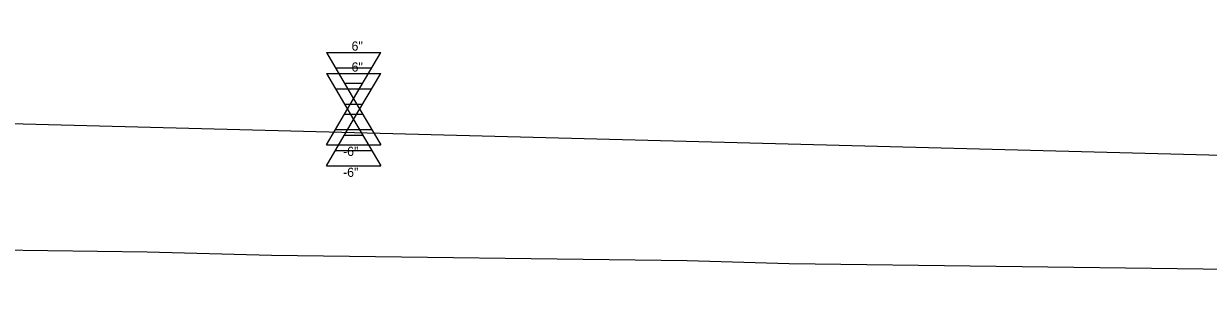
# Model space of a CAD drawing. Extents: x 573468 to 580768, y -57414 to -51768.
# Drawn here: x 574547.3 to 574611.5, y -53062.3 to -53047.5 of the extents above; entities that cross this region are included whole.
import ezdxf

# ---------------------------------------------------------------- set-up
doc = ezdxf.new("R2010")
doc.units = 0
for name, color, linetype in [('Exist Vertical Profile Ground Line', 7, 'Continuous'), ('Pattern 2', 7, 'Continuous'), ('Prop Vertical Profile Grade', 7, 'Continuous'), ('Scratch_Level_0', 7, 'Continuous')]:
    doc.layers.add(name, color=color, linetype=linetype)

msp = doc.modelspace()

# ---------------------------------------------------------------- linework, layer by layer
at = {"layer": 'Exist Vertical Profile Ground Line'}
msp.add_lwpolyline([(574543.255, -53059.77), (574554.026, -53059.906), (574560.775, -53060.086), (574583.28, -53060.379), (574588.793, -53060.537), (574611.208, -53060.826), (574616.517, -53060.941), (574629.403, -53061.136), (574635.759, -53061.316), (574658.007, -53061.658), (574661.307, -53061.757), (574673.813, -53062.023), (574681.74, -53062.264)], dxfattribs=at)
at = {"layer": 'Pattern 2'}
for p, q in [((574563.748, -53050.244), (574566.68, -53050.244)), ((574563.748, -53050.244), (574565.214, -53052.744)), ((574565.214, -53052.744), (574566.68, -53050.244)), ((574564.236, -53051.078), (574566.191, -53051.078)), ((574564.725, -53051.911), (574565.703, -53051.911)), ((574563.748, -53055.244), (574565.214, -53052.744)), ((574565.214, -53052.744), (574566.68, -53055.244)), ((574564.725, -53053.578), (574565.703, -53053.578)), ((574564.236, -53054.411), (574566.191, -53054.411)), ((574563.748, -53055.244), (574566.68, -53055.244))]:
    msp.add_line(p, q, dxfattribs=at)
at = {"layer": 'Prop Vertical Profile Grade'}
msp.add_line((574340.214, -53047.545), (574855.214, -53061.042), dxfattribs=at)
at = {"layer": 'Scratch_Level_0'}
for p, q in [((574563.748, -53049.109), (574566.68, -53049.109)), ((574563.748, -53049.109), (574565.214, -53051.609)), ((574565.214, -53051.609), (574566.68, -53049.109)), ((574564.236, -53049.943), (574566.191, -53049.943)), ((574564.725, -53050.776), (574565.703, -53050.776)), ((574563.748, -53054.109), (574565.214, -53051.609)), ((574565.214, -53051.609), (574566.68, -53054.109)), ((574564.725, -53052.443), (574565.703, -53052.443)), ((574564.236, -53053.276), (574566.191, -53053.276)), ((574563.748, -53054.109), (574566.68, -53054.109))]:
    msp.add_line(p, q, dxfattribs=at)

# ---------------------------------------------------------------- texts
at = {"layer": 'Pattern 2'}
for s, p in [('6"', (574565.101, -53050.143)), ('-6"', (574564.64, -53055.847))]:
    msp.add_text(s, height=0.5, rotation=360, dxfattribs=at).set_placement(p)
at = {"layer": 'Scratch_Level_0'}
for s, p in [('6"', (574565.101, -53049.008)), ('-6"', (574564.64, -53054.712))]:
    msp.add_text(s, height=0.5, dxfattribs=at).set_placement(p)

doc.saveas('drawing.dxf')
